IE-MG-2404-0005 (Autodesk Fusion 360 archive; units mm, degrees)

design "IS-MG-2404-0007" references "LED", "Digitus_DN-651107_LAN-Switch x2", "2 SFP SLOT", "DIP Switch", "8 ports ethernet", "6 holes POWER", "M2.4 Screw", "USB Type C Port (SMD Type) (1)"
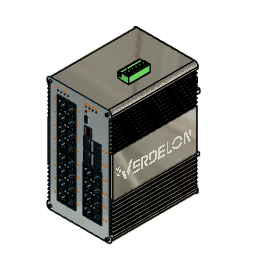
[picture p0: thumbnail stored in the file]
sketch "Sketch1" plane through (0, 0, 0) normal (0, 1, 0) x axis (1, 0, 0)
  line L1 (85, 0) -> (5, 0)
  line L2 (90, -155) -> (90, -5)
  line L3 (5, -160) -> (85, -160)
  line L4 (0, -5) -> (0, -155)
  arc A1 centre (85, -5) radius 5 clockwise from (85, 0) to (90, -5)
  arc A2 centre (5, -5) radius 5 clockwise from (0, -5) to (5, 0)
  arc A3 centre (85, -155) radius 5 clockwise from (90, -155) to (85, -160)
  arc A4 centre (5, -155) radius 5 clockwise from (5, -160) to (0, -155)
  point P1 (0, 0)
  point P2 (0, 0)
  point P3 (90, 0)
  point P4 (0, -160)
  horizontal L1
  vertical L2
  horizontal L3
  vertical L4
  coincident P1 P2
  coincident P3 L1
  coincident P3 L2
  tangent L1 A1
  tangent L2 A1
  coincident P2 L1
  coincident P2 L4
  tangent L1 A2
  tangent L4 A2
  equal A1 A2
  tangent L2 A3
  tangent L3 A3
  equal A1 A3
  coincident P4 L3
  coincident P4 L4
  tangent L3 A4
  tangent L4 A4
  equal A1 A4
  dimension "d1" distance P2 P4 = 160
  dimension "d2" distance P2 P3 = 90
  dimension "d3" radius A1 = 5
extrude "Extrude1" new body sketch "Sketch1" along normal blind 120
sketch "Sketch2" plane through (0, 0, 0) normal (0, -1, 0) x axis (1, 0, 0)
  line L1 (85, 0) -> (5, 0)
  line L2 (90, 155) -> (90, 5)
  line L3 (5, 160) -> (85, 160)
  line L4 (45, 80) -> (45, 160)
  line L5 (45, 80) -> (0, 80)
  line L6 (3.4641, 53) -> (0, 51)
  line L7 (3.4641, 50) -> (0, 48)
  line L8 (3.4641, 53) -> (3.4641, 50)
  line L9 (0, 51) -> (0, 48)
  line L10 (3.4641, 45) -> (0, 43)
  line L11 (0, 46) -> (0, 43)
  line L12 (3.4641, 48) -> (3.4641, 45)
  line L13 (3.4641, 48) -> (0, 46)
  line L14 (3.4641, 40) -> (0, 38)
  line L15 (0, 41) -> (0, 38)
  line L16 (3.4641, 43) -> (3.4641, 40)
  line L17 (3.4641, 43) -> (0, 41)
  line L18 (3.4641, 35) -> (0, 33)
  line L19 (0, 36) -> (0, 33)
  line L20 (3.4641, 38) -> (3.4641, 35)
  line L21 (3.4641, 38) -> (0, 36)
  line L22 (3.4641, 30) -> (0, 28)
  line L23 (0, 31) -> (0, 28)
  line L24 (3.4641, 33) -> (3.4641, 30)
  line L25 (3.4641, 33) -> (0, 31)
  line L26 (3.4641, 25) -> (0, 23)
  line L27 (0, 26) -> (0, 23)
  line L28 (3.4641, 28) -> (3.4641, 25)
  line L29 (3.4641, 28) -> (0, 26)
  line L30 (3.4641, 20) -> (0, 18)
  line L31 (0, 21) -> (0, 18)
  line L32 (3.4641, 23) -> (3.4641, 20)
  line L33 (3.4641, 23) -> (0, 21)
  line L34 (3.4641, 15) -> (0, 13)
  line L35 (0, 16) -> (0, 13)
  line L36 (3.4641, 18) -> (3.4641, 15)
  line L37 (3.4641, 18) -> (0, 16)
  line L38 (3.4641, 10) -> (0, 8)
  line L39 (0, 11) -> (0, 8)
  line L40 (3.4641, 13) -> (3.4641, 10)
  line L41 (3.4641, 13) -> (0, 11)
  line L42 (0, 129) -> (0, 132)
  line L43 (0, 149) -> (0, 152)
  line L44 (0, 109) -> (0, 112)
  line L45 (3.4641, 115) -> (0, 117)
  line L46 (3.4641, 112) -> (0, 114)
  line L47 (0, 119) -> (0, 122)
  line L48 (3.4641, 137) -> (3.4641, 140)
  line L49 (3.4641, 150) -> (0, 152)
  line L50 (3.4641, 142) -> (0, 144)
  line L51 (3.4641, 127) -> (0, 129)
  line L52 (0, 114) -> (0, 117)
  line L53 (3.4641, 122) -> (3.4641, 125)
  line L54 (3.4641, 142) -> (3.4641, 145)
  line L55 (3.4641, 135) -> (0, 137)
  line L56 (3.4641, 110) -> (0, 112)
  line L57 (3.4641, 132) -> (0, 134)
  line L58 (3.4641, 117) -> (0, 119)
  line L59 (0, 134) -> (0, 137)
  line L60 (3.4641, 117) -> (3.4641, 120)
  line L61 (3.4641, 130) -> (0, 132)
  line L62 (0, 144) -> (0, 147)
  line L63 (3.4641, 147) -> (0, 149)
  line L64 (3.4641, 147) -> (3.4641, 150)
  line L65 (3.4641, 122) -> (0, 124)
  line L66 (0, 124) -> (0, 127)
  line L67 (3.4641, 125) -> (0, 127)
  line L68 (3.4641, 107) -> (0, 109)
  line L69 (3.4641, 107) -> (3.4641, 110)
  line L70 (3.4641, 140) -> (0, 142)
  line L71 (3.4641, 145) -> (0, 147)
  line L72 (3.4641, 112) -> (3.4641, 115)
  line L73 (3.4641, 137) -> (0, 139)
  line L74 (0, 139) -> (0, 142)
  line L75 (3.4641, 132) -> (3.4641, 135)
  line L76 (3.4641, 120) -> (0, 122)
  line L77 (3.4641, 127) -> (3.4641, 130)
  line L78 (86.5359, 135) -> (90, 137)
  line L79 (90, 144) -> (90, 147)
  line L80 (90, 149) -> (90, 152)
  line L81 (90, 124) -> (90, 127)
  line L82 (86.5359, 120) -> (90, 122)
  line L83 (86.5359, 107) -> (90, 109)
  line L84 (86.5359, 117) -> (90, 119)
  line L85 (86.5359, 137) -> (90, 139)
  line L86 (86.5359, 122) -> (90, 124)
  line L87 (86.5359, 117) -> (86.5359, 120)
  line L88 (90, 114) -> (90, 117)
  line L89 (86.5359, 127) -> (86.5359, 130)
  line L90 (86.5359, 115) -> (90, 117)
  line L91 (86.5359, 130) -> (90, 132)
  line L92 (86.5359, 147) -> (86.5359, 150)
  line L93 (86.5359, 142) -> (86.5359, 145)
  line L94 (86.5359, 142) -> (90, 144)
  line L95 (90, 109) -> (90, 112)
  line L96 (90, 134) -> (90, 137)
  line L97 (86.5359, 107) -> (86.5359, 110)
  line L98 (86.5359, 132) -> (86.5359, 135)
  line L99 (86.5359, 112) -> (86.5359, 115)
  line L100 (86.5359, 137) -> (86.5359, 140)
  line L101 (86.5359, 110) -> (90, 112)
  line L102 (86.5359, 132) -> (90, 134)
  line L103 (86.5359, 145) -> (90, 147)
  line L104 (86.5359, 150) -> (90, 152)
  line L105 (90, 129) -> (90, 132)
  line L106 (86.5359, 112) -> (90, 114)
  line L107 (86.5359, 147) -> (90, 149)
  line L108 (90, 119) -> (90, 122)
  line L109 (86.5359, 127) -> (90, 129)
  line L110 (86.5359, 125) -> (90, 127)
  line L111 (86.5359, 122) -> (86.5359, 125)
  line L112 (90, 139) -> (90, 142)
  line L113 (86.5359, 140) -> (90, 142)
  line L114 (86.5359, 48) -> (86.5359, 45)
  line L115 (90, 46) -> (90, 43)
  line L116 (90, 36) -> (90, 33)
  line L117 (90, 41) -> (90, 38)
  line L118 (86.5359, 15) -> (90, 13)
  line L119 (90, 21) -> (90, 18)
  line L120 (86.5359, 53) -> (90, 51)
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  point P14 (45, 160)
  point P17 (0, 51)
  point P56 (0, 109)
  point P18 (3.4641, 53)
  point P88 (3.4641, 107)
  point P19 (0, 48)
  point P54 (0, 112)
  point P20 (3.4641, 50)
  point P55 (3.4641, 110)
  point P21 (0, 43)
  point P62 (0, 117)
  point P22 (3.4641, 45)
  point P61 (3.4641, 115)
  point P23 (0, 46)
  point P59 (0, 114)
  point P24 (3.4641, 48)
  point P60 (3.4641, 112)
  point P25 (0, 38)
  point P58 (0, 122)
  point P26 (3.4641, 40)
  point P53 (3.4641, 120)
  point P27 (0, 41)
  point P57 (0, 119)
  point P28 (3.4641, 43)
  point P85 (3.4641, 117)
  point P29 (0, 33)
  point P81 (0, 127)
  point P30 (3.4641, 35)
  point P78 (3.4641, 125)
  point P31 (0, 36)
  point P80 (0, 124)
  point P32 (3.4641, 38)
  point P86 (3.4641, 122)
  point P33 (0, 28)
  point P79 (0, 132)
  point P34 (3.4641, 30)
  point P87 (3.4641, 130)
  point P35 (0, 31)
  point P82 (0, 129)
  point P36 (3.4641, 33)
  point P75 (3.4641, 127)
  point P37 (0, 23)
  point P83 (0, 137)
  point P38 (3.4641, 25)
  point P77 (3.4641, 135)
  point P39 (0, 26)
  point P84 (0, 134)
  point P40 (3.4641, 28)
  point P76 (3.4641, 132)
  point P41 (0, 18)
  point P70 (0, 142)
  point P42 (3.4641, 20)
  point P68 (3.4641, 140)
  point P43 (0, 21)
  point P74 (0, 139)
  point P44 (3.4641, 23)
  point P71 (3.4641, 137)
  point P45 (0, 13)
  point P63 (0, 147)
  point P46 (3.4641, 15)
  point P67 (3.4641, 145)
  point P47 (0, 16)
  point P73 (0, 144)
  point P48 (3.4641, 18)
  point P65 (3.4641, 142)
  point P49 (0, 8)
  point P69 (0, 152)
  point P50 (3.4641, 10)
  point P64 (3.4641, 150)
  point P51 (0, 11)
  point P66 (0, 149)
  point P52 (3.4641, 13)
  point P72 (3.4641, 147)
  point P11 (5, 160)
  point P163 (85, 160)
  point P12 (0, 155)
  point P120 (90, 155)
  point P127 (90, 51)
  point P130 (86.5359, 53)
  point P128 (90, 48)
  point P140 (86.5359, 50)
  point P132 (90, 43)
  point P159 (86.5359, 45)
  point P153 (90, 46)
  point P150 (86.5359, 48)
  point P152 (90, 38)
  point P146 (86.5359, 40)
  point P135 (90, 41)
  point P138 (86.5359, 43)
  point P133 (90, 33)
  point P134 (86.5359, 35)
  point P129 (90, 36)
  point P131 (86.5359, 38)
  point P143 (90, 28)
  point P144 (86.5359, 30)
  point P142 (90, 31)
  point P147 (86.5359, 33)
  point P149 (90, 23)
  point P160 (86.5359, 25)
  point P162 (90, 26)
  point P161 (86.5359, 28)
  point P155 (90, 18)
  point P148 (86.5359, 20)
  point P154 (90, 21)
  point P151 (86.5359, 23)
  point P145 (90, 13)
  point P141 (86.5359, 15)
  point P157 (90, 16)
  point P156 (86.5359, 18)
  point P158 (90, 8)
  point P136 (86.5359, 10)
  point P137 (90, 11)
  point P139 (86.5359, 13)
  point P91 (86.5359, 120)
  point P93 (90, 112)
  point P119 (86.5359, 110)
  point P115 (90, 109)
  point P116 (90, 119)
  point P118 (90, 122)
  point P123 (90, 114)
  point P108 (86.5359, 112)
  point P97 (86.5359, 115)
  point P110 (90, 117)
  point P99 (90, 147)
  point P111 (86.5359, 150)
  point P104 (86.5359, 142)
  point P105 (90, 149)
  point P101 (86.5359, 145)
  point P103 (86.5359, 140)
  point P95 (90, 152)
  point P98 (90, 142)
  point P96 (86.5359, 137)
  point P100 (86.5359, 147)
  point P117 (90, 144)
  point P126 (90, 139)
  point P106 (86.5359, 127)
  point P107 (86.5359, 132)
  point P114 (86.5359, 135)
  point P102 (86.5359, 125)
  point P121 (90, 132)
  point P113 (90, 124)
  point P124 (90, 127)
  point P112 (90, 129)
  point P125 (90, 137)
  point P89 (90, 134)
  point P122 (86.5359, 117)
  point P94 (86.5359, 122)
  point P90 (86.5359, 130)
  point P92 (86.5359, 107)
  midpoint L3 P14
  perpendicular L3 L4
  perpendicular L4 L5
  symmetric L5 P17 P56
  symmetric L5 P18 P88
  symmetric L5 P19 P54
  symmetric L5 P20 P55
  symmetric L5 P21 P62
  symmetric L5 P22 P61
  symmetric L5 P23 P59
  symmetric L5 P24 P60
  symmetric L5 P25 P58
  symmetric L5 P26 P53
  symmetric L5 P27 P57
  symmetric L5 P28 P85
  symmetric L5 P29 P81
  symmetric L5 P30 P78
  symmetric L5 P31 P80
  symmetric L5 P32 P86
  symmetric L5 P33 P79
  symmetric L5 P34 P87
  symmetric L5 P35 P82
  symmetric L5 P36 P75
  symmetric L5 P37 P83
  symmetric L5 P38 P77
  symmetric L5 P39 P84
  symmetric L5 P40 P76
  symmetric L5 P41 P70
  symmetric L5 P42 P68
  symmetric L5 P43 P74
  symmetric L5 P44 P71
  symmetric L5 P45 P63
  symmetric L5 P46 P67
  symmetric L5 P47 P73
  symmetric L5 P48 P65
  symmetric L5 P49 P69
  symmetric L5 P50 P64
  symmetric L5 P51 P66
  symmetric L5 P52 P72
  symmetric P11 L4 P163
  symmetric P12 L4 P120
  symmetric L4 P17 P127
  symmetric L4 P18 P130
  symmetric L4 P19 P128
  symmetric L4 P20 P140
  symmetric L4 P21 P132
  symmetric L4 P22 P159
  symmetric L4 P23 P153
  symmetric L4 P24 P150
  symmetric L4 P25 P152
  symmetric L4 P26 P146
  symmetric L4 P27 P135
  symmetric L4 P28 P138
  symmetric L4 P29 P133
  symmetric L4 P30 P134
  symmetric L4 P31 P129
  symmetric L4 P32 P131
  symmetric L4 P33 P143
  symmetric L4 P34 P144
  symmetric L4 P35 P142
  symmetric L4 P36 P147
  symmetric L4 P37 P149
  symmetric L4 P38 P160
  symmetric L4 P39 P162
  symmetric L4 P40 P161
  symmetric L4 P41 P155
  symmetric L4 P42 P148
  symmetric L4 P43 P154
  symmetric L4 P44 P151
  symmetric L4 P45 P145
  symmetric L4 P46 P141
  symmetric L4 P47 P157
  symmetric L4 P48 P156
  symmetric L4 P49 P158
  symmetric L4 P50 P136
  symmetric L4 P51 P137
  symmetric L4 P52 P139
  symmetric L4 P53 P91
  symmetric L4 P54 P93
  symmetric L4 P55 P119
  symmetric L4 P56 P115
  symmetric L4 P57 P116
  symmetric L4 P58 P118
  symmetric L4 P59 P123
  symmetric L4 P60 P108
  symmetric L4 P61 P97
  symmetric L4 P62 P110
  symmetric L4 P63 P99
  symmetric L4 P64 P111
  symmetric L4 P65 P104
  symmetric L4 P66 P105
  symmetric L4 P67 P101
  symmetric L4 P68 P103
  symmetric L4 P69 P95
  symmetric L4 P70 P98
  symmetric L4 P71 P96
  symmetric L4 P72 P100
  symmetric L4 P73 P117
  symmetric L4 P74 P126
  symmetric L4 P75 P106
  symmetric L4 P76 P107
  symmetric L4 P77 P114
  symmetric L4 P78 P102
  symmetric L4 P79 P121
  symmetric L4 P80 P113
  symmetric L4 P81 P124
  symmetric L4 P82 P112
  symmetric L4 P83 P125
  symmetric L4 P84 P89
  symmetric L4 P85 P122
  symmetric L4 P86 P94
  symmetric L4 P87 P90
  symmetric L4 P88 P92
  dimension "d6" distance P17 P18 = 2
  dimension "d16" distance L5 P18 = 27
  dimension "d10" R-Pattern1-uDistance = 0
  dimension "d11" R-Pattern1-vDistance = -3
  dimension "d14" R-Pattern2-uDistance = 0
  dimension "d15" R-Pattern2-vDistance = -40
extrude "Extrude3" cut sketch "Sketch2" against normal blind 120
sketch "Sketch3" plane through (0, 0, 0) normal (0, -1, 0) x axis (1, 0, 0)
  line L1 (0, 18) -> (3.4641, 20)
  line L2 (0, 16) -> (0, 18)
  line L3 (3.4641, 18) -> (0, 16)
  line L4 (3.4641, 15) -> (3.4641, 18)
  line L5 (0, 13) -> (3.4641, 15)
  line L6 (0, 11) -> (0, 13)
  line L7 (3.4641, 13) -> (0, 11)
  line L8 (3.4641, 10) -> (3.4641, 13)
  line L9 (0, 8) -> (3.4641, 10)
  line L10 (0, 5) -> (0, 8)
  line L11 (85, 0) -> (5, 0)
  line L12 (90, 8) -> (90, 5)
  line L13 (86.5359, 10) -> (90, 8)
  line L14 (86.5359, 13) -> (86.5359, 10)
  line L15 (90, 11) -> (86.5359, 13)
  line L16 (90, 13) -> (90, 11)
  line L17 (86.5359, 15) -> (90, 13)
  line L18 (86.5359, 18) -> (86.5359, 15)
  line L19 (90, 16) -> (86.5359, 18)
  line L20 (90, 18) -> (90, 16)
  line L21 (86.5359, 20) -> (90, 18)
  line L22 (86.5359, 23) -> (86.5359, 20)
  line L23 (90, 21) -> (86.5359, 23)
  line L24 (90, 23) -> (90, 21)
  line L25 (86.5359, 25) -> (90, 23)
  line L26 (86.5359, 28) -> (86.5359, 25)
  line L27 (90, 26) -> (86.5359, 28)
  line L28 (90, 28) -> (90, 26)
  line L29 (86.5359, 30) -> (90, 28)
  line L30 (86.5359, 33) -> (86.5359, 30)
  line L31 (90, 31) -> (86.5359, 33)
  line L32 (90, 33) -> (90, 31)
  line L33 (86.5359, 35) -> (90, 33)
  line L34 (86.5359, 38) -> (86.5359, 35)
  line L35 (90, 36) -> (86.5359, 38)
  line L36 (90, 38) -> (90, 36)
  line L37 (86.5359, 40) -> (90, 38)
  line L38 (86.5359, 43) -> (86.5359, 40)
  line L39 (90, 41) -> (86.5359, 43)
  line L40 (90, 43) -> (90, 41)
  line L41 (86.5359, 45) -> (90, 43)
  line L42 (86.5359, 48) -> (86.5359, 45)
  line L43 (90, 46) -> (86.5359, 48)
  line L44 (90, 48) -> (90, 46)
  line L45 (86.5359, 50) -> (90, 48)
  line L46 (86.5359, 53) -> (86.5359, 50)
  line L47 (90, 51) -> (86.5359, 53)
  line L48 (90, 109) -> (90, 51)
  line L49 (86.5359, 107) -> (90, 109)
  line L50 (86.5359, 110) -> (86.5359, 107)
  line L51 (90, 112) -> (86.5359, 110)
  line L52 (90, 114) -> (90, 112)
  line L53 (86.5359, 112) -> (90, 114)
  line L54 (86.5359, 115) -> (86.5359, 112)
  line L55 (90, 117) -> (86.5359, 115)
  line L56 (90, 119) -> (90, 117)
  line L57 (86.5359, 117) -> (90, 119)
  line L58 (86.5359, 120) -> (86.5359, 117)
  line L59 (90, 122) -> (86.5359, 120)
  line L60 (90, 124) -> (90, 122)
  line L61 (86.5359, 122) -> (90, 124)
  line L62 (86.5359, 125) -> (86.5359, 122)
  line L63 (90, 127) -> (86.5359, 125)
  line L64 (90, 129) -> (90, 127)
  line L65 (86.5359, 127) -> (90, 129)
  line L66 (86.5359, 130) -> (86.5359, 127)
  line L67 (90, 132) -> (86.5359, 130)
  line L68 (90, 134) -> (90, 132)
  line L69 (86.5359, 132) -> (90, 134)
  line L70 (86.5359, 135) -> (86.5359, 132)
  line L71 (90, 137) -> (86.5359, 135)
  line L72 (90, 139) -> (90, 137)
  line L73 (86.5359, 137) -> (90, 139)
  line L74 (86.5359, 140) -> (86.5359, 137)
  line L75 (90, 142) -> (86.5359, 140)
  line L76 (90, 144) -> (90, 142)
  line L77 (86.5359, 142) -> (90, 144)
  line L78 (86.5359, 145) -> (86.5359, 142)
  line L79 (90, 147) -> (86.5359, 145)
  line L80 (90, 149) -> (90, 147)
  line L81 (86.5359, 147) -> (90, 149)
  line L82 (86.5359, 150) -> (86.5359, 147)
  line L83 (90, 152) -> (86.5359, 150)
  line L84 (90, 155) -> (90, 152)
  line L85 (5, 160) -> (85, 160)
  line L86 (0, 152) -> (0, 155)
  line L87 (3.4641, 150) -> (0, 152)
  line L88 (3.4641, 147) -> (3.4641, 150)
  line L89 (0, 149) -> (3.4641, 147)
  line L90 (0, 147) -> (0, 149)
  line L91 (3.4641, 145) -> (0, 147)
  line L92 (3.4641, 142) -> (3.4641, 145)
  line L93 (0, 144) -> (3.4641, 142)
  line L94 (0, 142) -> (0, 144)
  line L95 (3.4641, 140) -> (0, 142)
  line L96 (3.4641, 137) -> (3.4641, 140)
  line L97 (0, 139) -> (3.4641, 137)
  line L98 (0, 137) -> (0, 139)
  line L99 (3.4641, 135) -> (0, 137)
  line L100 (3.4641, 132) -> (3.4641, 135)
  line L101 (0, 134) -> (3.4641, 132)
  line L102 (0, 132) -> (0, 134)
  line L103 (3.4641, 130) -> (0, 132)
  line L104 (3.4641, 127) -> (3.4641, 130)
  line L105 (0, 129) -> (3.4641, 127)
  line L106 (0, 127) -> (0, 129)
  line L107 (3.4641, 125) -> (0, 127)
  line L108 (3.4641, 122) -> (3.4641, 125)
  line L109 (0, 124) -> (3.4641, 122)
  line L110 (0, 122) -> (0, 124)
  line L111 (3.4641, 120) -> (0, 122)
  line L112 (3.4641, 117) -> (3.4641, 120)
  line L113 (0, 119) -> (3.4641, 117)
  line L114 (0, 117) -> (0, 119)
  line L115 (3.4641, 115) -> (0, 117)
  line L116 (3.4641, 112) -> (3.4641, 115)
  line L117 (0, 114) -> (3.4641, 112)
  line L118 (0, 112) -> (0, 114)
  line L119 (3.4641, 110) -> (0, 112)
  line L120 (3.4641, 107) -> (3.4641, 110)
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  point P158 (45, 160)
  point P173 (48, 108.7134)
  point P256 (48, 108.7134)
  point P172 (58, 108.7134)
  point P255 (58, 108.7134)
  point P254 (58, 108.7134)
  point P257 (48, 108.7134)
  point P171 (58, 97.7134)
  point P252 (58, 97.7134)
  point P253 (58, 97.7134)
  point P161 (14.2, 143.8)
  point P164 (14.2, 16.2)
  point P162 (40, 143.8)
  point P168 (57.7, 21.2)
  point P169 (57.7, 35.7)
  point P170 (48, 35.7)
  point P175 (57.21, 141.6534)
  point P176 (57.21, 129.7834)
  point P174 (50.21, 141.6534)
  point P178 (52.01, 143.6534)
  point P183 (54.01, 148.6534)
  midpoint L85 P158
  coincident P173 P256
  coincident P172 P255
  coincident P172 P254
  coincident P173 P257
  coincident P171 P252
  coincident P171 P253
  dimension "d21" distance P161 P164 = 127.6
  dimension "d22" distance P161 P162 = 25.8
  dimension "d23" distance = 5
  dimension "d24" distance P168 P169 = 14.5
  dimension "d25" distance P169 P170 = 9.7
  dimension "d30" distance = 5
  dimension "d31" distance = 8
  dimension "d32" distance P171 P172 = 11
  dimension "d33" distance P172 P173 = 10
  dimension "d34" distance = 2
  dimension "d35" distance = 8.94
  dimension "d36" distance = 3.21
  dimension "d37" distance = 8
  dimension "d38" distance P175 P176 = 11.87
  dimension "d39" distance P174 P175 = 7
  dimension "d42" distance = 1
  dimension "d43" diameter = 1
  dimension "d44" distance = 2
  dimension "d45" distance = 1.8
  dimension "d46" diameter = 1.5
  dimension "d47" distance = 3
  dimension "d48" distance = 1.5
  dimension "d53" diameter = 1.5
  dimension "d54" distance P178 P183 = 5
  dimension "d55" distance P178 P183 = 2
  dimension "d60" diameter = 1.7
  dimension "d69" radius = 1.25
  dimension "d77" radius = 0.75
  dimension "d82" distance = 5.5
  dimension "d83" distance = 5.5
  dimension "d169" distance = 14.5
  dimension "d51" R-Pattern2-uDistance = 6
  dimension "d52" R-Pattern2-vDistance = 0
  dimension "d58" R-Pattern3-uDistance = 6
  dimension "d59" R-Pattern3-vDistance = 0
  dimension "d63" R-Pattern4-uDistance = 80
  dimension "d64" R-Pattern4-vDistance = 0
  dimension "d67" R-Pattern5-uDistance = 0
  dimension "d68" R-Pattern5-vDistance = -150
sketch "Sketch7" plane through (0, 0, 0) normal (0, -1, 0) x axis (1, 0, 0)
  line L1 (0, 18) -> (3.4641, 20)
  line L2 (0, 16) -> (0, 18)
  line L3 (3.4641, 18) -> (0, 16)
  line L4 (3.4641, 15) -> (3.4641, 18)
  line L5 (0, 13) -> (3.4641, 15)
  line L6 (0, 11) -> (0, 13)
  line L7 (3.4641, 13) -> (0, 11)
  line L8 (3.4641, 10) -> (3.4641, 13)
  line L9 (0, 8) -> (3.4641, 10)
  line L10 (0, 5) -> (0, 8)
  line L11 (85, 0) -> (5, 0)
  line L12 (90, 8) -> (90, 5)
  line L13 (86.5359, 10) -> (90, 8)
  line L14 (86.5359, 13) -> (86.5359, 10)
  line L15 (90, 11) -> (86.5359, 13)
  line L16 (90, 13) -> (90, 11)
  line L17 (86.5359, 15) -> (90, 13)
  line L18 (86.5359, 18) -> (86.5359, 15)
  line L19 (90, 16) -> (86.5359, 18)
  line L20 (90, 18) -> (90, 16)
  line L21 (86.5359, 20) -> (90, 18)
  line L22 (86.5359, 23) -> (86.5359, 20)
  line L23 (90, 21) -> (86.5359, 23)
  line L24 (90, 23) -> (90, 21)
  line L25 (86.5359, 25) -> (90, 23)
  line L26 (86.5359, 28) -> (86.5359, 25)
  line L27 (90, 26) -> (86.5359, 28)
  line L28 (90, 28) -> (90, 26)
  line L29 (86.5359, 30) -> (90, 28)
  line L30 (86.5359, 33) -> (86.5359, 30)
  line L31 (90, 31) -> (86.5359, 33)
  line L32 (90, 33) -> (90, 31)
  line L33 (86.5359, 35) -> (90, 33)
  line L34 (86.5359, 38) -> (86.5359, 35)
  line L35 (90, 36) -> (86.5359, 38)
  line L36 (90, 38) -> (90, 36)
  line L37 (86.5359, 40) -> (90, 38)
  line L38 (86.5359, 43) -> (86.5359, 40)
  line L39 (90, 41) -> (86.5359, 43)
  line L40 (90, 43) -> (90, 41)
  line L41 (86.5359, 45) -> (90, 43)
  line L42 (86.5359, 48) -> (86.5359, 45)
  line L43 (90, 46) -> (86.5359, 48)
  line L44 (90, 48) -> (90, 46)
  line L45 (86.5359, 50) -> (90, 48)
  line L46 (86.5359, 53) -> (86.5359, 50)
  line L47 (90, 51) -> (86.5359, 53)
  line L48 (90, 109) -> (90, 51)
  line L49 (86.5359, 107) -> (90, 109)
  line L50 (86.5359, 110) -> (86.5359, 107)
  line L51 (90, 112) -> (86.5359, 110)
  line L52 (90, 114) -> (90, 112)
  line L53 (86.5359, 112) -> (90, 114)
  line L54 (86.5359, 115) -> (86.5359, 112)
  line L55 (90, 117) -> (86.5359, 115)
  line L56 (90, 119) -> (90, 117)
  line L57 (86.5359, 117) -> (90, 119)
  line L58 (86.5359, 120) -> (86.5359, 117)
  line L59 (90, 122) -> (86.5359, 120)
  line L60 (90, 124) -> (90, 122)
  line L61 (86.5359, 122) -> (90, 124)
  line L62 (86.5359, 125) -> (86.5359, 122)
  line L63 (90, 127) -> (86.5359, 125)
  line L64 (90, 129) -> (90, 127)
  line L65 (86.5359, 127) -> (90, 129)
  line L66 (86.5359, 130) -> (86.5359, 127)
  line L67 (90, 132) -> (86.5359, 130)
  line L68 (90, 134) -> (90, 132)
  line L69 (86.5359, 132) -> (90, 134)
  line L70 (86.5359, 135) -> (86.5359, 132)
  line L71 (90, 137) -> (86.5359, 135)
  line L72 (90, 139) -> (90, 137)
  line L73 (86.5359, 137) -> (90, 139)
  line L74 (86.5359, 140) -> (86.5359, 137)
  line L75 (90, 142) -> (86.5359, 140)
  line L76 (90, 144) -> (90, 142)
  line L77 (86.5359, 142) -> (90, 144)
  line L78 (86.5359, 145) -> (86.5359, 142)
  line L79 (90, 147) -> (86.5359, 145)
  line L80 (90, 149) -> (90, 147)
  line L81 (86.5359, 147) -> (90, 149)
  line L82 (86.5359, 150) -> (86.5359, 147)
  line L83 (90, 152) -> (86.5359, 150)
  line L84 (90, 155) -> (90, 152)
  line L85 (5, 160) -> (85, 160)
  line L86 (0, 152) -> (0, 155)
  line L87 (3.4641, 150) -> (0, 152)
  line L88 (3.4641, 147) -> (3.4641, 150)
  line L89 (0, 149) -> (3.4641, 147)
  line L90 (0, 147) -> (0, 149)
  line L91 (3.4641, 145) -> (0, 147)
  line L92 (3.4641, 142) -> (3.4641, 145)
  line L93 (0, 144) -> (3.4641, 142)
  line L94 (0, 142) -> (0, 144)
  line L95 (3.4641, 140) -> (0, 142)
  line L96 (3.4641, 137) -> (3.4641, 140)
  line L97 (0, 139) -> (3.4641, 137)
  line L98 (0, 137) -> (0, 139)
  line L99 (3.4641, 135) -> (0, 137)
  line L100 (3.4641, 132) -> (3.4641, 135)
  line L101 (0, 134) -> (3.4641, 132)
  line L102 (0, 132) -> (0, 134)
  line L103 (3.4641, 130) -> (0, 132)
  line L104 (3.4641, 127) -> (3.4641, 130)
  line L105 (0, 129) -> (3.4641, 127)
  line L106 (0, 127) -> (0, 129)
  line L107 (3.4641, 125) -> (0, 127)
  line L108 (3.4641, 122) -> (3.4641, 125)
  line L109 (0, 124) -> (3.4641, 122)
  line L110 (0, 122) -> (0, 124)
  line L111 (3.4641, 120) -> (0, 122)
  line L112 (3.4641, 117) -> (3.4641, 120)
  line L113 (0, 119) -> (3.4641, 117)
  line L114 (0, 117) -> (0, 119)
  line L115 (3.4641, 115) -> (0, 117)
  line L116 (3.4641, 112) -> (3.4641, 115)
  line L117 (0, 114) -> (3.4641, 112)
  line L118 (0, 112) -> (0, 114)
  line L119 (3.4641, 110) -> (0, 112)
  line L120 (3.4641, 107) -> (3.4641, 110)
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  point P11 (0, 8)
  point P158 (0, 8)
  point P164 (45, 0)
  coincident P11 P158
  midpoint L11 P164
  dimension "d170" = 0
  dimension "d171" distance ORIGIN L9 = 0
extrude "Extrude5" cut sketch "Sketch7" against normal blind 1.5
sketch "Sketch8" plane through (0, 120, 0) normal (0, 1, 0) x axis (-1, 0, 0)
  line L1 (-3.4641, 20) -> (0, 18)
  line L2 (-3.4641, 23) -> (-3.4641, 20)
  line L3 (0, 21) -> (-3.4641, 23)
  line L4 (0, 23) -> (0, 21)
  line L5 (-3.4641, 25) -> (0, 23)
  line L6 (-3.4641, 28) -> (-3.4641, 25)
  line L7 (0, 26) -> (-3.4641, 28)
  line L8 (0, 28) -> (0, 26)
  line L9 (-3.4641, 30) -> (0, 28)
  line L10 (-3.4641, 33) -> (-3.4641, 30)
  line L11 (0, 31) -> (-3.4641, 33)
  line L12 (0, 33) -> (0, 31)
  line L13 (-3.4641, 35) -> (0, 33)
  line L14 (-3.4641, 38) -> (-3.4641, 35)
  line L15 (0, 36) -> (-3.4641, 38)
  line L16 (0, 38) -> (0, 36)
  line L17 (-3.4641, 40) -> (0, 38)
  line L18 (-3.4641, 43) -> (-3.4641, 40)
  line L19 (0, 41) -> (-3.4641, 43)
  line L20 (0, 43) -> (0, 41)
  line L21 (-3.4641, 45) -> (0, 43)
  line L22 (-3.4641, 48) -> (-3.4641, 45)
  line L23 (0, 46) -> (-3.4641, 48)
  line L24 (0, 48) -> (0, 46)
  line L25 (-3.4641, 50) -> (0, 48)
  line L26 (-3.4641, 53) -> (-3.4641, 50)
  line L27 (0, 51) -> (-3.4641, 53)
  line L28 (0, 109) -> (0, 51)
  line L29 (-3.4641, 107) -> (0, 109)
  line L30 (-3.4641, 110) -> (-3.4641, 107)
  line L31 (0, 112) -> (-3.4641, 110)
  line L32 (0, 114) -> (0, 112)
  line L33 (-3.4641, 112) -> (0, 114)
  line L34 (-3.4641, 115) -> (-3.4641, 112)
  line L35 (0, 117) -> (-3.4641, 115)
  line L36 (0, 119) -> (0, 117)
  line L37 (-3.4641, 117) -> (0, 119)
  line L38 (-3.4641, 120) -> (-3.4641, 117)
  line L39 (0, 122) -> (-3.4641, 120)
  line L40 (0, 124) -> (0, 122)
  line L41 (-3.4641, 122) -> (0, 124)
  line L42 (-3.4641, 125) -> (-3.4641, 122)
  line L43 (0, 127) -> (-3.4641, 125)
  line L44 (0, 129) -> (0, 127)
  line L45 (-3.4641, 127) -> (0, 129)
  line L46 (-3.4641, 130) -> (-3.4641, 127)
  line L47 (0, 132) -> (-3.4641, 130)
  line L48 (0, 134) -> (0, 132)
  line L49 (-3.4641, 132) -> (0, 134)
  line L50 (-3.4641, 135) -> (-3.4641, 132)
  line L51 (0, 137) -> (-3.4641, 135)
  line L52 (0, 139) -> (0, 137)
  line L53 (-3.4641, 137) -> (0, 139)
  line L54 (-3.4641, 140) -> (-3.4641, 137)
  line L55 (0, 142) -> (-3.4641, 140)
  line L56 (0, 144) -> (0, 142)
  line L57 (-3.4641, 142) -> (0, 144)
  line L58 (-3.4641, 145) -> (-3.4641, 142)
  line L59 (0, 147) -> (-3.4641, 145)
  line L60 (0, 149) -> (0, 147)
  line L61 (-3.4641, 147) -> (0, 149)
  line L62 (-3.4641, 150) -> (-3.4641, 147)
  line L63 (0, 152) -> (-3.4641, 150)
  line L64 (0, 155) -> (0, 152)
  line L65 (-85, 160) -> (-5, 160)
  line L66 (-90, 152) -> (-90, 155)
  line L67 (-86.5359, 150) -> (-90, 152)
  line L68 (-86.5359, 147) -> (-86.5359, 150)
  line L69 (-90, 149) -> (-86.5359, 147)
  line L70 (-90, 147) -> (-90, 149)
  line L71 (-86.5359, 145) -> (-90, 147)
  line L72 (-86.5359, 142) -> (-86.5359, 145)
  line L73 (-90, 144) -> (-86.5359, 142)
  line L74 (-90, 142) -> (-90, 144)
  line L75 (-86.5359, 140) -> (-90, 142)
  line L76 (-86.5359, 137) -> (-86.5359, 140)
  line L77 (-90, 139) -> (-86.5359, 137)
  line L78 (-90, 137) -> (-90, 139)
  line L79 (-86.5359, 135) -> (-90, 137)
  line L80 (-86.5359, 132) -> (-86.5359, 135)
  line L81 (-90, 134) -> (-86.5359, 132)
  line L82 (-90, 132) -> (-90, 134)
  line L83 (-86.5359, 130) -> (-90, 132)
  line L84 (-86.5359, 127) -> (-86.5359, 130)
  line L85 (-90, 129) -> (-86.5359, 127)
  line L86 (-90, 127) -> (-90, 129)
  line L87 (-86.5359, 125) -> (-90, 127)
  line L88 (-86.5359, 122) -> (-86.5359, 125)
  line L89 (-90, 124) -> (-86.5359, 122)
  line L90 (-90, 122) -> (-90, 124)
  line L91 (-86.5359, 120) -> (-90, 122)
  line L92 (-86.5359, 117) -> (-86.5359, 120)
  line L93 (-90, 119) -> (-86.5359, 117)
  line L94 (-90, 117) -> (-90, 119)
  line L95 (-86.5359, 115) -> (-90, 117)
  line L96 (-86.5359, 112) -> (-86.5359, 115)
  line L97 (-90, 114) -> (-86.5359, 112)
  line L98 (-90, 112) -> (-90, 114)
  line L99 (-86.5359, 110) -> (-90, 112)
  line L100 (-86.5359, 107) -> (-86.5359, 110)
  line L101 (-90, 109) -> (-86.5359, 107)
  line L102 (-90, 51) -> (-90, 109)
  line L103 (-86.5359, 53) -> (-90, 51)
  line L104 (-86.5359, 50) -> (-86.5359, 53)
  line L105 (-90, 48) -> (-86.5359, 50)
  line L106 (-90, 46) -> (-90, 48)
  line L107 (-86.5359, 48) -> (-90, 46)
  line L108 (-86.5359, 45) -> (-86.5359, 48)
  line L109 (-90, 43) -> (-86.5359, 45)
  line L110 (-90, 41) -> (-90, 43)
  line L111 (-86.5359, 43) -> (-90, 41)
  line L112 (-86.5359, 40) -> (-86.5359, 43)
  line L113 (-90, 38) -> (-86.5359, 40)
  line L114 (-90, 36) -> (-90, 38)
  line L115 (-86.5359, 38) -> (-90, 36)
  line L116 (-86.5359, 35) -> (-86.5359, 38)
  line L117 (-90, 33) -> (-86.5359, 35)
  line L118 (-90, 31) -> (-90, 33)
  line L119 (-86.5359, 33) -> (-90, 31)
  line L120 (-86.5359, 30) -> (-86.5359, 33)
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  point P143 (-90, 8)
  point P158 (-90, 8)
  point P72 (-90, 152)
  point P159 (-90, 152)
  coincident P143 P158
  coincident P72 P159
  dimension "d174" = 0
  dimension "d175" = 0
extrude "Extrude6" cut sketch "Sketch8" against normal blind 1.5
sketch "Sketch9" plane through (0, 0, 0) normal (0, -1, 0) x axis (1, 0, 0)
  line L1 (86.5359, 150) -> (86.5359, 10)
  line L2 (90, 152) -> (86.5359, 150)
  line L3 (90, 155) -> (90, 152)
  line L4 (5, 160) -> (85, 160)
  line L5 (0, 152) -> (0, 155)
  line L6 (3.4641, 150) -> (0, 152)
  line L7 (3.4641, 10) -> (3.4641, 150)
  line L8 (0, 8) -> (3.4641, 10)
  line L9 (0, 5) -> (0, 8)
  line L10 (85, 0) -> (5, 0)
  line L11 (90, 8) -> (90, 5)
  line L12 (86.5359, 10) -> (90, 8)
  line L13 (45, 80) -> (45, 160)
  line L14 (45, 80) -> (3.4641, 80)
  line L15 (40, 143.8) -> (14.2, 143.8)
  line L16 (40, 16.2) -> (40, 143.8)
  line L17 (14.2, 16.2) -> (40, 16.2)
  line L18 (14.2, 143.8) -> (14.2, 16.2)
  line L19 (75.8, 16.2) -> (50, 16.2)
  line L20 (75.8, 80) -> (75.8, 16.2)
  line L21 (50, 80) -> (75.8, 80)
  line L22 (50, 16.2) -> (50, 80)
  line L23 (74.096, 82) -> (51.704, 82)
  line L24 (74.85, 95.746) -> (74.85, 82.754)
  line L25 (51.704, 96.5) -> (74.096, 96.5)
  line L26 (50.95, 82.754) -> (50.95, 95.746)
  line L27 (62.9, 71.3263) -> (62.9, 80)
  line L28 (50.95, 98.7538) -> (50.95, 111.746)
  line L29 (74.096, 97.9992) -> (51.704, 97.9998)
  line L30 (74.85, 111.746) -> (74.85, 98.7532)
  line L31 (51.704, 112.5) -> (74.096, 112.5)
  line L32 (61.95, 114.5) -> (51.95, 114.5)
  line L33 (61.95, 125.5) -> (61.95, 114.5)
  line L34 (51.95, 125.5) -> (61.95, 125.5)
  line L35 (51.95, 114.5) -> (51.95, 125.5)
  line L36 (54.41, 129) -> (53.7, 129)
  line L37 (55.66, 136.66) -> (55.66, 130.25)
  line L38 (53.7, 137.91) -> (54.41, 137.91)
  line L39 (52.45, 130.25) -> (52.45, 136.66)
  line L40 (54.055, 136) -> (54.055, 137.91)
  arc A1 centre (85, 155) radius 5 clockwise from (85, 160) to (90, 155)
  arc A2 centre (5, 155) radius 5 clockwise from (0, 155) to (5, 160)
  arc A3 centre (5, 5) radius 5 clockwise from (5, 0) to (0, 5)
  arc A4 centre (85, 5) radius 5 clockwise from (90, 5) to (85, 0)
  arc A5 centre (53.7, 136.66) radius 1.25 clockwise from (52.45, 136.66) to (53.7, 137.91)
  arc A6 centre (54.41, 136.66) radius 1.25 clockwise from (54.41, 137.91) to (55.66, 136.66)
  arc A7 centre (53.7, 130.25) radius 1.25 clockwise from (53.7, 129) to (52.45, 130.25)
  arc A8 centre (54.41, 130.25) radius 1.25 clockwise from (55.66, 130.25) to (54.41, 129)
  circle C1 centre (54.055, 142.91) radius 1
  circle C2 centre (15.2, 148.8) radius 0.75
  circle C3 centre (19.8667, 148.8) radius 0.75
  circle C4 centre (24.5333, 148.8) radius 0.75
  circle C5 centre (29.2, 148.8) radius 0.75
  circle C6 centre (68.2, 148.8) radius 0.75
  circle C7 centre (54.2, 148.8) radius 0.75
  circle C8 centre (63.5333, 148.8) radius 0.75
  circle C9 centre (58.8667, 148.8) radius 0.75
  circle C10 centre (5, 155) radius 1.25
  circle C11 centre (85, 155) radius 1.25
  circle C12 centre (5, 5) radius 1.25
  circle C13 centre (85, 5) radius 1.25
  arc A9 centre (51.704, 82.754) radius 0.754 clockwise from (51.704, 82) to (50.95, 82.754)
  arc A10 centre (74.096, 82.754) radius 0.754 clockwise from (74.85, 82.754) to (74.096, 82)
  arc A11 centre (74.096, 95.746) radius 0.754 clockwise from (74.096, 96.5) to (74.85, 95.746)
  arc A12 centre (51.704, 95.746) radius 0.754 clockwise from (50.95, 95.746) to (51.704, 96.5)
  arc A13 centre (51.704, 98.7538) radius 0.754 clockwise from (51.704, 97.9998) to (50.95, 98.7538)
  arc A14 centre (51.704, 111.746) radius 0.754 clockwise from (50.95, 111.746) to (51.704, 112.5)
  arc A15 centre (74.096, 111.746) radius 0.754 clockwise from (74.096, 112.5) to (74.85, 111.746)
  arc A16 centre (74.096, 98.7532) radius 0.754 clockwise from (74.85, 98.7532) to (74.096, 97.9992)
  point P22 (45, 160)
  point P23 (3.4641, 80)
  point P36 (62.9, 80)
  point P44 (52.45, 137.91)
  point P43 (55.66, 137.91)
  point P42 (55.66, 129)
  point P58 (54.055, 137.91)
  point P57 (54.055, 142.91)
  point P33 (50.95, 82)
  point P34 (74.85, 82)
  point P35 (74.85, 96.5)
  point P27 (40, 16.2)
  point P28 (14.2, 16.2)
  point P25 (14.2, 143.8)
  point P29 (50, 16.2)
  point P30 (75.8, 16.2)
  point P31 (75.8, 80)
  point P39 (61.95, 114.5)
  point P40 (61.95, 125.5)
  point P41 (51.95, 125.5)
  point P45 (53.7, 137.91)
  point P60 (15.2, 148.8)
  midpoint L4 P22
  perpendicular L4 L13
  midpoint L7 P23
  perpendicular L13 L14
  horizontal L15
  vertical L16
  horizontal L17
  vertical L18
  symmetric L14 L15 L17
  horizontal L19
  vertical L20
  horizontal L21
  vertical L22
  collinear L17 L19
  horizontal L23
  vertical L24
  horizontal L25
  vertical L26
  midpoint L21 P36
  perpendicular L21 L27
  horizontal L32
  vertical L33
  horizontal L34
  vertical L35
  horizontal L36
  vertical L37
  horizontal L38
  vertical L39
  coincident P44 L38
  coincident P44 L39
  tangent L38 A5
  tangent L39 A5
  coincident P43 L37
  coincident P43 L38
  tangent L37 A6
  tangent L38 A6
  equal A5 A6
  tangent L36 A7
  tangent L39 A7
  equal A5 A7
  coincident P42 L36
  coincident P42 L37
  tangent L36 A8
  tangent L37 A8
  equal A5 A8
  midpoint L38 P58
  perpendicular L38 L40
  coincident P57 L40
  concentric A2 C10
  coincident P33 L23
  coincident P33 L26
  tangent L23 A9
  tangent L26 A9
  coincident P34 L23
  coincident P34 L24
  tangent L23 A10
  tangent L24 A10
  equal A9 A10
  coincident P35 L24
  coincident P35 L25
  tangent L24 A11
  tangent L25 A11
  equal A9 A11
  tangent L25 A12
  tangent L26 A12
  equal A9 A12
  tangent L28 A13
  tangent L29 A13
  equal A9 A13
  tangent L28 A14
  tangent L31 A14
  equal A9 A14
  tangent L30 A15
  tangent L31 A15
  equal A9 A15
  tangent L29 A16
  tangent L30 A16
  equal A9 A16
  collinear L26 L28
  collinear L24 L30
  dimension "d178" distance P27 P28 = 25.8
  dimension "d179" distance P25 P28 = 127.6
  dimension "d180" distance P29 P30 = 25.8
  dimension "d181" distance P30 P31 = 63.8
  dimension "d182" distance L13 L16 = 5
  dimension "d183" distance L13 L22 = 5
  dimension "d184" distance P33 P34 = 23.9
  dimension "d185" distance P34 P35 = 14.5
  dimension "d186" distance L21 L23 = 2
  dimension "d191" distance P39 P40 = 11
  dimension "d192" distance P40 P41 = 10
  dimension "d193" distance L28 L35 = 1
  dimension "d194" distance L31 L32 = 2
  dimension "d195" distance P42 P43 = 8.91
  dimension "d196" distance P43 P44 = 3.21
  dimension "d197" radius A5 = 1.25
  dimension "d198" distance L35 L39 = 0.5
  dimension "d199" distance L34 L36 = 3.5
  dimension "d200" diameter C1 = 2
  dimension "d201" distance P45 P57 = 5
  dimension "d202" diameter C2 = 1.5
  dimension "d203" distance L18 P60 = 1
  dimension "d204" distance L15 P60 = 5
  dimension "d213" diameter C10 = 2.5
  dimension "d262" radius A9 = 0.754
  dimension "d207" R-Pattern2-uDistance = 14
  dimension "d208" R-Pattern2-vDistance = 0
  dimension "d211" R-Pattern3-uDistance = 39
  dimension "d212" R-Pattern3-vDistance = 0
  dimension "d216" R-Pattern4-uDistance = 80
  dimension "d217" R-Pattern4-vDistance = 0
  dimension "d220" R-Pattern5-uDistance = 0
  dimension "d221" R-Pattern5-vDistance = -150
  dimension "d189" R-Pattern1-uDistance = 0
  dimension "d190" R-Pattern1-vDistance = 16
extrude "Extrude7" cut sketch "Sketch9" profile of L14 L15 L16 L17 L18 L19 L20 L21 L22 L23 L24 L25 L26 L28 L29 L30 L31 L32 L33 L34 L35 L36 L37 L38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 against normal blind 10
shell "Shell2" innerThickness 1
sketch "Sketch10" plane through (0, 0, 160) normal (0, 0, 1) x axis (-1, 0, 0)
  line L1 (-85, 0) -> (-5, 0)
  line L2 (-85, -120) -> (-85, 0)
  line L3 (-5, -120) -> (-85, -120)
  line L4 (-5, 0) -> (-5, -120)
  line L5 (-45, -60) -> (-45, -120)
  line L6 (-45, -60) -> (-5, -60)
  line L7 (-68.6, -75) -> (-60, -75)
  line L8 (-68.6, -45) -> (-68.6, -75)
  line L9 (-60, -45) -> (-68.6, -45)
  line L10 (-60, -75) -> (-60, -45)
  point P6 (-45, -120)
  point P7 (-5, -60)
  point P10 (-68.6, -75)
  point P11 (-68.6, -45)
  point P9 (-60, -75)
  midpoint L3 P6
  perpendicular L3 L5
  midpoint L4 P7
  perpendicular L4 L6
  horizontal L7
  vertical L8
  horizontal L9
  vertical L10
  symmetric L6 L7 L9
  dimension "d237" distance P10 P11 = 30
  dimension "d238" distance P9 P10 = 8.6
  dimension "d239" distance L5 L10 = 15
extrude "Extrude8" cut sketch "Sketch10" profile of L7 L8 L9 L10 against normal blind 5
component_insert "Component Insert19"
joint "Assemble5" alignAngle 0 alignOffsetX 0 alignOffsetY 0 alignOffsetZ 2.5
rectangular_pattern "00000000-0000-0000-0000-000000000000" uSpaceDistance 14 vSpaceDistance 0
rectangular_pattern "00000000-0000-0000-0000-000000000000" uSpaceDistance 39 vSpaceDistance 0
component_insert "Component Insert16"
position "Position12"
component_insert "Component Insert17"
joint "Assemble6" alignAngle -90 alignOffsetX 0 alignOffsetY 0 alignOffsetZ 3.9
rectangular_pattern "00000000-0000-0000-0000-000000000000" uSpaceDistance 80 vSpaceDistance 0
rectangular_pattern "00000000-0000-0000-0000-000000000000" uSpaceDistance -150 vSpaceDistance 0
component_insert "Component Insert20"
position "Position13"
rectangular_pattern "00000000-0000-0000-0000-000000000000" uSpaceDistance 63.8 vSpaceDistance 0
rectangular_pattern "00000000-0000-0000-0000-000000000000" uSpaceDistance -35.8 vSpaceDistance 0
component_insert "Component Insert21"
position "Position14"
rectangular_pattern "00000000-0000-0000-0000-000000000000" uSpaceDistance -16 vSpaceDistance 0
component_insert "Component Insert22"
component_insert "Component Insert23"
component_insert "Component Insert24"
decal "Decal1"
decal "Decal2"
position "Position15"
sketch "Sketch11" plane through (0, 0, 0) normal (0, -1, 0) x axis (1, 0, 0)
  dimension "d267" = 2
  dimension "d268" = 2
  dimension "d269" = 2
  dimension "d270" = 2
  dimension "d271" = 2
  dimension "d272" = 2
  dimension "d273" = 2
  dimension "d274" = 2
  dimension "d275" = 2
  dimension "d276" = 2
  dimension "d277" = 2
  dimension "d278" = 2
  dimension "d279" = 2
  dimension "d280" = 2
  dimension "d281" = 2
  dimension "d282" = 2
  dimension "d283" = 2
  dimension "d284" = 2
  dimension "d285" = 2
  dimension "d286" = 2
  dimension "d287" = 2
  dimension "d288" = 2
  dimension "d289" = 2
  dimension "d290" = 2
  dimension "d291" = 2
  dimension "d292" = 2
  dimension "d293" = 2
  dimension "d294" = 2
  dimension "d295" = 2
  dimension "d296" = 2
  dimension "d297" = 1
  dimension "d298" = 1
  dimension "d299" = 1
  dimension "d300" = 1
  dimension "d301" = 1
  dimension "d302" = 1
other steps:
joint_origin "JointOrigin6"
joint_origin "JointOrigin7"

design "LED"
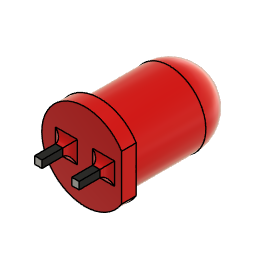
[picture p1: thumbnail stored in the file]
description: STEP AP214
part number: LED

design "Digitus_DN-651107_LAN-Switch x2"
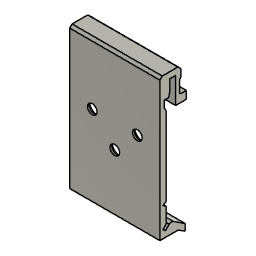
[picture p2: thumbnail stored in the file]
description: STEP AP214
part number: Digitus_DN-651107_LAN-Switch x2

design "8 ports ethernet"
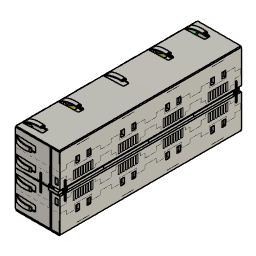
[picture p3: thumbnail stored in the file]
description: STEP AP214
part number: 8 ports ethernet

design "2 SFP SLOT"
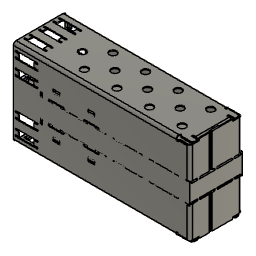
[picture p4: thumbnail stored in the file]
description: STEP AP214
part number: SFP SLOT

design "USB Type C Port (SMD Type) (1)"
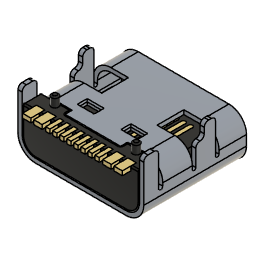
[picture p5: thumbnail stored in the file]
description: STEP AP214
part number: USB Type C Port (SMD Type) (1)

design "6 holes POWER"
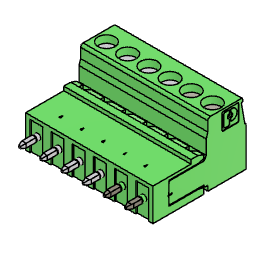
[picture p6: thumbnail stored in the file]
description: STEP AP214
part number: POWER

design "DIP Switch"
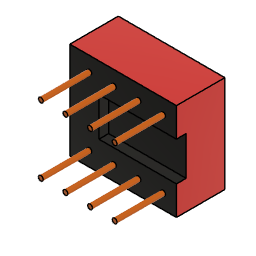
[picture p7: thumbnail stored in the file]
description: STEP AP214
part number: DIP Switch

design "M2.4 Screw"
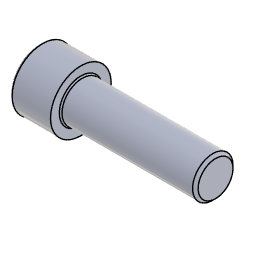
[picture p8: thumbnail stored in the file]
description: STEP AP214
part number: M2.4 Screw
